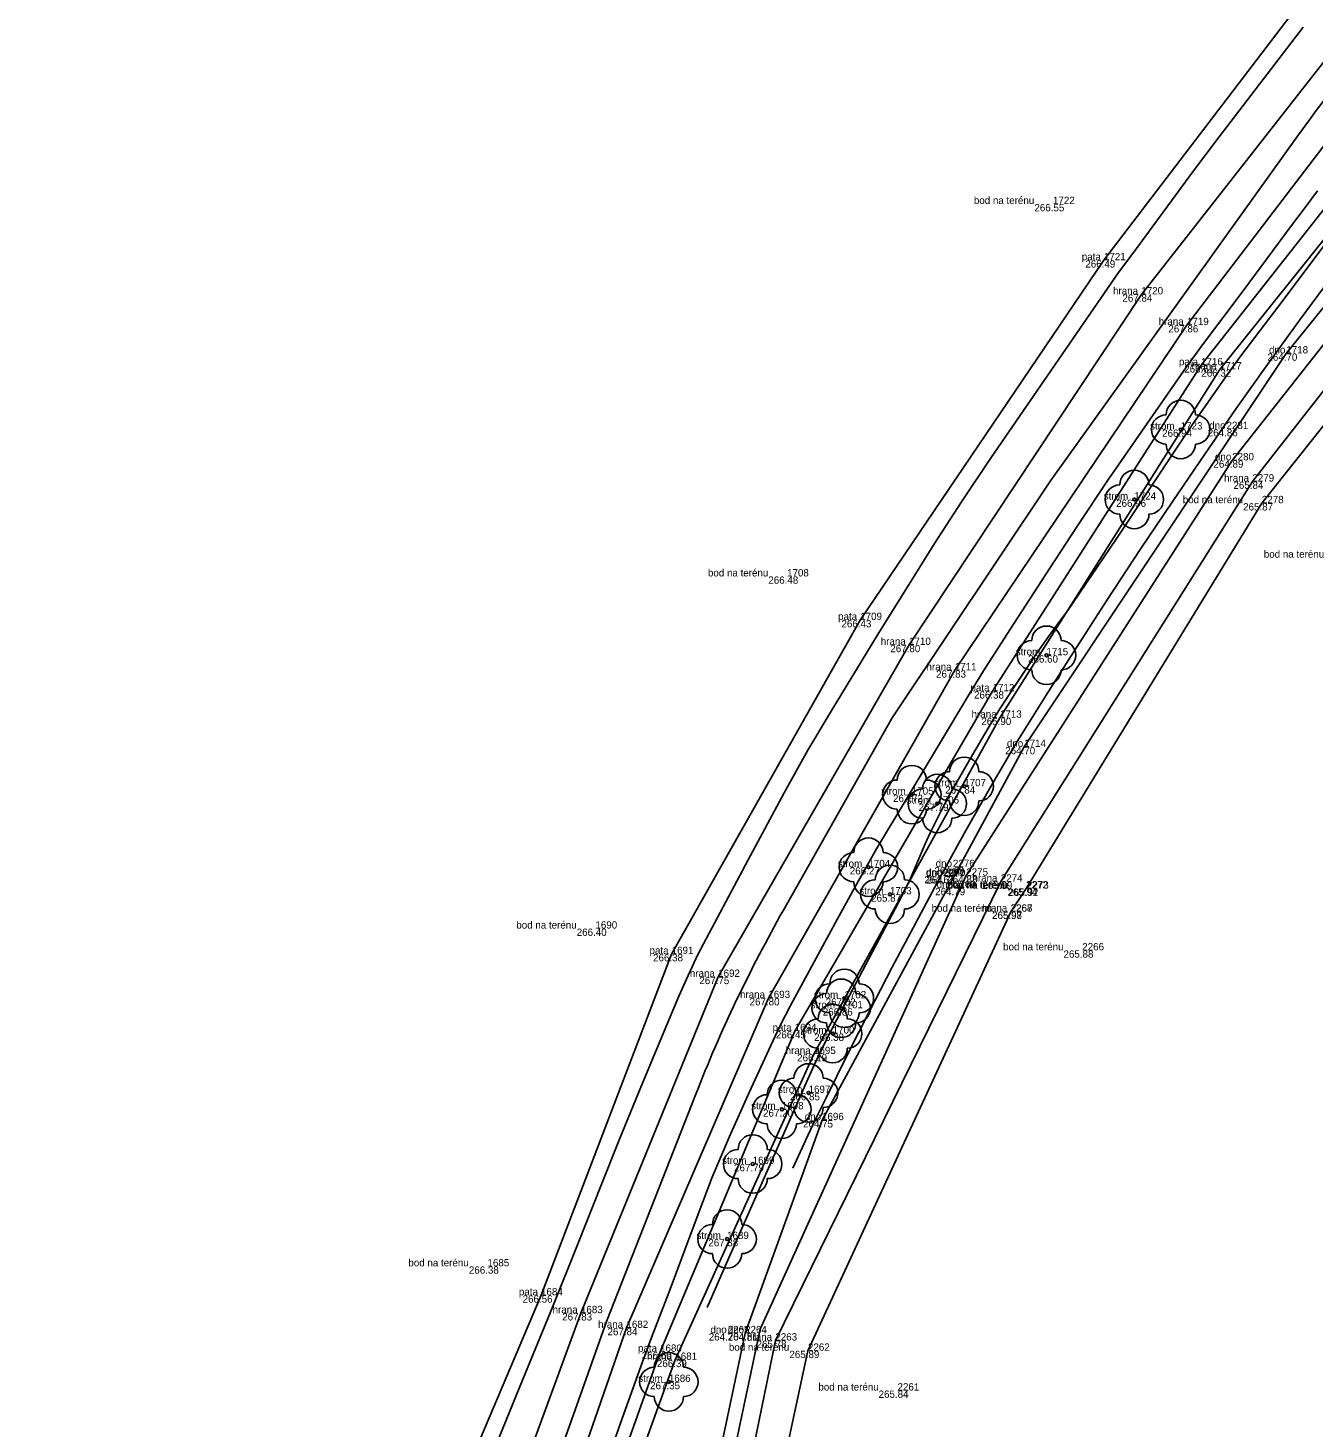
# Model space of a CAD drawing. Extents: x -567962 to -566460, y -1093720 to -1089838.
# Drawn here: x -567008.8 to -566920.9, y -1090322.4 to -1090226.7 of the extents above; entities that cross this region are included whole.
import ezdxf

# ---------------------------------------------------------------- set-up
doc = ezdxf.new("R2010")
doc.units = 0
for name, color, linetype in [('0_osa hráze', 7, 'Continuous'), ('bod_znacka', 7, 'Continuous'), ('cislo_bodu', 7, 'Continuous'), ('Doměření - kraj pole', 7, 'Continuous'), ('hlavni_vrst', 7, 'Continuous'), ('hrana_L', 7, 'Continuous'), ('hrana_P', 7, 'Continuous'), ('kod_bodu', 7, 'Continuous'), ('norm_vrst', 7, 'Continuous'), ('stromy', 7, 'Continuous'), ('vyska_bodu', 7, 'Continuous')]:
    doc.layers.add(name, color=color, linetype=linetype)

msp = doc.modelspace()

# ---------------------------------------------------------------- linework, layer by layer
at = {"layer": '0_osa hráze'}
for points in [[(-566921.908, -1090233.941), (-566938.917, -1090257.673), (-566949.741, -1090273.867), (-566957.169, -1090287.016)], [(-566963.167, -1090299.613), (-566969.274, -1090315.144), (-566984.132, -1090357.048), (-566990.346, -1090376.417)]]:
    msp.add_lwpolyline(points, dxfattribs=at)
for centre, radius, start, end in [((-566843.631, -1090289.76), 96.141, 137.41218, 144.50722), ((-566870.102, -1090336.202), 100, 150.5371, 158.53747)]:
    msp.add_arc(centre, radius, start, end, dxfattribs=at)
at = {"layer": 'bod_znacka'}
for p, q in [((-566938.74, -1090238.73), (-566938.74, -1090238.73)), ((-566935.26, -1090242.58), (-566935.26, -1090242.58)), ((-566932.7, -1090244.91), (-566932.7, -1090244.91)), ((-566929.58, -1090247.01), (-566929.58, -1090247.01)), ((-566928.62, -1090249.76), (-566928.62, -1090249.76)), ((-566922.79, -1090248.95), (-566922.79, -1090248.95)), ((-566927.33, -1090250.04), (-566927.33, -1090250.04)), ((-566930.01, -1090254.15), (-566930.01, -1090254.15)), ((-566926.88, -1090254.12), (-566926.88, -1090254.12)), ((-566926.49, -1090256.26), (-566926.49, -1090256.26)), ((-566925.11, -1090257.71), (-566925.11, -1090257.71)), ((-566933.18, -1090258.94), (-566933.18, -1090258.94)), ((-566924.46, -1090259.19), (-566924.46, -1090259.19)), ((-566956.92, -1090264.2), (-566956.92, -1090264.2)), ((-566951.92, -1090267.18), (-566951.92, -1090267.18)), ((-566948.58, -1090268.88), (-566948.58, -1090268.88)), ((-566939.19, -1090269.59), (-566939.19, -1090269.59)), ((-566945.45, -1090270.62), (-566945.45, -1090270.62)), ((-566942.87, -1090272.05), (-566942.87, -1090272.05)), ((-566942.37, -1090273.86), (-566942.37, -1090273.86)), ((-566940.71, -1090275.86), (-566940.71, -1090275.86)), ((-566948.39, -1090279.12), (-566948.39, -1090279.12)), ((-566944.81, -1090278.55), (-566944.81, -1090278.55)), ((-566946.65, -1090279.73), (-566946.65, -1090279.73)), ((-566951.36, -1090284.08), (-566951.36, -1090284.08)), ((-566945.58, -1090284.07), (-566945.58, -1090284.07)), ((-566946.25, -1090284.68), (-566946.25, -1090284.68)), ((-566946.22, -1090284.7), (-566946.22, -1090284.7)), ((-566944.67, -1090284.66), (-566944.67, -1090284.66)), ((-566942.31, -1090285.07), (-566942.31, -1090285.07)), ((-566949.89, -1090285.94), (-566949.89, -1090285.94)), ((-566945.51, -1090285.5), (-566945.51, -1090285.5)), ((-566940.57, -1090285.53), (-566940.57, -1090285.53)), ((-566940.52, -1090285.55), (-566940.52, -1090285.55)), ((-566941.64, -1090287.12), (-566941.64, -1090287.12)), ((-566941.63, -1090287.13), (-566941.63, -1090287.13)), ((-566970.02, -1090288.28), (-566970.02, -1090288.28)), ((-566936.74, -1090289.77), (-566936.74, -1090289.77)), ((-566964.81, -1090290.02), (-566964.81, -1090290.02)), ((-566961.63, -1090291.58), (-566961.63, -1090291.58)), ((-566958.2, -1090293.03), (-566958.2, -1090293.03)), ((-566953.22, -1090293.73), (-566953.22, -1090293.73)), ((-566953, -1090293.05), (-566953, -1090293.05)), ((-566956.4, -1090295.29), (-566956.4, -1090295.29)), ((-566953.8, -1090295.46), (-566953.8, -1090295.46)), ((-566955.08, -1090296.86), (-566955.08, -1090296.86)), ((-566955.45, -1090299.52), (-566955.45, -1090299.52)), ((-566957.28, -1090300.64), (-566957.28, -1090300.64)), ((-566954.53, -1090301.38), (-566954.53, -1090301.38)), ((-566959.27, -1090304.38), (-566959.27, -1090304.38)), ((-566961.02, -1090309.51), (-566961.02, -1090309.51)), ((-566977.4, -1090311.38), (-566977.4, -1090311.38)), ((-566973.74, -1090313.36), (-566973.74, -1090313.36)), ((-566971.01, -1090314.58), (-566971.01, -1090314.58)), ((-566967.9, -1090315.59), (-566967.9, -1090315.59)), ((-566960.98, -1090315.95), (-566960.98, -1090315.95)), ((-566959.79, -1090315.95), (-566959.79, -1090315.95)), ((-566957.72, -1090316.45), (-566957.72, -1090316.45)), ((-566965.6, -1090317.22), (-566965.6, -1090317.22)), ((-566955.49, -1090317.15), (-566955.49, -1090317.15)), ((-566964.56, -1090317.77), (-566964.56, -1090317.77)), ((-566965, -1090319.28), (-566965, -1090319.28)), ((-566949.37, -1090319.87), (-566949.37, -1090319.87))]:
    msp.add_line(p, q, dxfattribs=at)
at = {"layer": 'Doměření - kraj pole'}
msp.add_lwpolyline([(-567047.906, -1090663.012), (-567047.627, -1090662.294), (-567014.86, -1090563.09), (-567002.362, -1090535.532), (-566955.49, -1090317.15), (-566941.63, -1090287.13), (-566940.57, -1090285.53), (-566924.46, -1090259.19), (-566900.35, -1090228.87), (-566877.72, -1090206.37), (-566851.19, -1090186.75), (-566766.44, -1090128.68), (-566717.21, -1090096.34), (-566711.98, -1090092.48)], dxfattribs=at)
at = {"layer": 'hlavni_vrst'}
msp.add_lwpolyline([(-566956.533, -1090304.653), (-566955.502, -1090302.437), (-566954.903, -1090301.184), (-566954.247, -1090299.843), (-566952.78, -1090296.901), (-566951.278, -1090293.935), (-566949.727, -1090290.928), (-566948.124, -1090287.878), (-566946.45, -1090284.76), (-566945.538, -1090283.095), (-566944.699, -1090281.582), (-566942.982, -1090278.562), (-566941.254, -1090275.609), (-566939.214, -1090272.309), (-566937.349, -1090269.367), (-566935.033, -1090265.79), (-566932.772, -1090262.358), (-566930.554, -1090259.048), (-566928.368, -1090255.839), (-566926.209, -1090252.725), (-566924.067, -1090249.701), (-566921.855, -1090246.641), (-566919.79, -1090243.854)], dxfattribs=at)
at = {"layer": 'hrana_L'}
for p, q in [((-566920.16, -1090222.76), (-566935.26, -1090242.58)), ((-566932.7, -1090244.91), (-566917.27, -1090225.23)), ((-566914.61, -1090227.38), (-566929.58, -1090247.01)), ((-566912.62, -1090229.4), (-566928.62, -1090249.76)), ((-566927.33, -1090250.04), (-566911.56, -1090230.31)), ((-566935.26, -1090242.58), (-566951.92, -1090267.18)), ((-566948.58, -1090268.88), (-566932.7, -1090244.91)), ((-566945.45, -1090270.62), (-566929.58, -1090247.01)), ((-566928.62, -1090249.76), (-566942.87, -1090272.05)), ((-566942.37, -1090273.86), (-566927.33, -1090250.04)), ((-566964.81, -1090290.02), (-566951.92, -1090267.18)), ((-566948.58, -1090268.88), (-566961.63, -1090291.58)), ((-566945.45, -1090270.62), (-566958.2, -1090293.03)), ((-566942.87, -1090272.05), (-566956.4, -1090295.29)), ((-566955.08, -1090296.86), (-566942.37, -1090273.86)), ((-566973.74, -1090313.36), (-566964.81, -1090290.02)), ((-566971.01, -1090314.58), (-566961.63, -1090291.58)), ((-566967.9, -1090315.59), (-566958.2, -1090293.03)), ((-566956.4, -1090295.29), (-566965.6, -1090317.22)), ((-566964.56, -1090317.77), (-566955.08, -1090296.86)), ((-566973.74, -1090313.36), (-566985.01, -1090340.01)), ((-566971.01, -1090314.58), (-566980.92, -1090341.55)), ((-566977.18, -1090342.32), (-566967.9, -1090315.59)), ((-566965.6, -1090317.22), (-566974.91, -1090343.39)), ((-566974.3, -1090344.62), (-566964.56, -1090317.77))]:
    msp.add_line(p, q, dxfattribs=at)
for points in [[(-567053.87, -1090661.84), (-567020.06, -1090563.34), (-567005.258, -1090534.966), (-566958.763, -1090315.674), (-566944.67, -1090284.66), (-566926.49, -1090256.26), (-566902.65, -1090226.03), (-566881.28, -1090203.14), (-566853.44, -1090182.668), (-566715.257, -1090089.634)], [(-567050.54, -1090661.95), (-567017.83, -1090562.99), (-567002.61, -1090535.52), (-566957.72, -1090316.45), (-566942.31, -1090285.07), (-566925.11, -1090257.71), (-566901.37, -1090227.4), (-566879.5, -1090205.23), (-566852.16, -1090184), (-566767.57, -1090126.99), (-566713.28, -1090090.76)], [(-567054.63, -1090661.3), (-567021.1, -1090563.26), (-567005.966, -1090534.719), (-566959.79, -1090315.95), (-566954.53, -1090301.38)]]:
    msp.add_lwpolyline(points, dxfattribs=at)
at = {"layer": 'hrana_P'}
for p, q in [((-566922.79, -1090248.95), (-566910.59, -1090233.83)), ((-566940.71, -1090275.86), (-566922.79, -1090248.95)), ((-566954.53, -1090301.38), (-566940.71, -1090275.86))]:
    msp.add_line(p, q, dxfattribs=at)
at = {"layer": 'norm_vrst'}
for points in [[(-566921.631, -1090226.636), (-566927.374, -1090234.13), (-566929.214, -1090236.565), (-566930.144, -1090237.821), (-566933.286, -1090242.113), (-566934.252, -1090243.42), (-566942.963, -1090256.062), (-566945.005, -1090259.092), (-566946.842, -1090261.952), (-566950.762, -1090268.239), (-566953.91, -1090273.403), (-566955.496, -1090276.071), (-566957.12, -1090278.988), (-566959.578, -1090283.574), (-566963.014, -1090290.057), (-566963.692, -1090291.478), (-566964.311, -1090292.906), (-566965.735, -1090296.276), (-566967.081, -1090299.517), (-566968.372, -1090302.673), (-566969.588, -1090305.72), (-566971.236, -1090309.907), (-566972.962, -1090314.167), (-566974.958, -1090319.037), (-566976.818, -1090323.639)], [(-566969.913, -1090326.583), (-566968.088, -1090321.464), (-566966.795, -1090317.901), (-566966.181, -1090316.247), (-566964.978, -1090313.119), (-566963.904, -1090310.25), (-566963.004, -1090307.815), (-566962.031, -1090305.286), (-566960.849, -1090302.498), (-566959.504, -1090299.484), (-566958.039, -1090296.283), (-566957.4, -1090294.915), (-566956.691, -1090293.534), (-566953.476, -1090287.621), (-566952.352, -1090285.575), (-566950.796, -1090282.831), (-566948.721, -1090279.329), (-566944.417, -1090272.172), (-566943.482, -1090270.658), (-566941.698, -1090267.861), (-566938.962, -1090263.63), (-566937.068, -1090260.735), (-566935.032, -1090257.687), (-566932.881, -1090254.561), (-566929.611, -1090249.872), (-566928.521, -1090248.361), (-566925.741, -1090244.665), (-566922.499, -1090240.286), (-566921.513, -1090238.972), (-566920.65, -1090237.841)], [(-566962.371, -1090314.194), (-566961.149, -1090311.363), (-566955.495, -1090298.587), (-566954.946, -1090297.363), (-566954.195, -1090295.83), (-566953.545, -1090294.534), (-566949.312, -1090286.501), (-566948.564, -1090285.069), (-566947.67, -1090282.913), (-566947.482, -1090282.482), (-566947.131, -1090281.722), (-566946.382, -1090280.231), (-566945.807, -1090279.129), (-566944.249, -1090276.398), (-566942.942, -1090274.189), (-566942.37, -1090273.243), (-566941.418, -1090271.796), (-566939.949, -1090269.611), (-566938.981, -1090268.225), (-566938.226, -1090267.192), (-566937.801, -1090266.624), (-566934.432, -1090261.656), (-566930.188, -1090255.265), (-566929.157, -1090253.738), (-566926.997, -1090250.63), (-566925.963, -1090249.21), (-566922.93, -1090245.222), (-566917.696, -1090238.209)]]:
    msp.add_lwpolyline(points, dxfattribs=at)
at = {"layer": 'stromy'}
for centre in [(-566930.01, -1090254.15), (-566933.18, -1090258.94), (-566939.19, -1090269.59), (-566944.81, -1090278.55), (-566948.39, -1090279.12), (-566946.65, -1090279.73), (-566951.36, -1090284.08), (-566949.89, -1090285.94), (-566953.22, -1090293.73), (-566953, -1090293.05), (-566953.8, -1090295.46), (-566955.45, -1090299.52), (-566957.28, -1090300.64), (-566959.27, -1090304.38), (-566961.02, -1090309.51), (-566965, -1090319.28)]:
    msp.add_circle(centre, 0.1, dxfattribs=at)
for centre, start, end in [((-566930.01, -1090253.15), 0, 180), ((-566931.01, -1090254.15), 90, 270), ((-566929.01, -1090254.15), 270, 90), ((-566930.01, -1090255.15), 180, 0), ((-566933.18, -1090257.94), 0, 180), ((-566934.18, -1090258.94), 90, 270), ((-566932.18, -1090258.94), 270, 90), ((-566933.18, -1090259.94), 180, 0), ((-566939.19, -1090268.59), 0, 180), ((-566940.19, -1090269.59), 90, 270), ((-566938.19, -1090269.59), 270, 90), ((-566939.19, -1090270.59), 180, 0), ((-566944.81, -1090277.55), 0, 180), ((-566948.39, -1090278.12), 0, 180), ((-566949.39, -1090279.12), 90, 270), ((-566946.65, -1090278.73), 0, 180), ((-566947.39, -1090279.12), 270, 90), ((-566945.81, -1090278.55), 90, 270), ((-566943.81, -1090278.55), 270, 90), ((-566947.65, -1090279.73), 90, 270), ((-566945.65, -1090279.73), 270, 90), ((-566948.39, -1090280.12), 180, 0), ((-566944.81, -1090279.55), 180, 0), ((-566946.65, -1090280.73), 180, 0), ((-566951.36, -1090283.08), 0, 180), ((-566952.36, -1090284.08), 90, 270), ((-566950.36, -1090284.08), 270, 90), ((-566949.89, -1090284.94), 0, 180), ((-566951.36, -1090285.08), 180, 0), ((-566950.89, -1090285.94), 90, 270), ((-566948.89, -1090285.94), 270, 90), ((-566949.89, -1090286.94), 180, 0), ((-566953.22, -1090292.73), 0, 180), ((-566953, -1090292.05), 0, 180), ((-566954.22, -1090293.73), 90, 270), ((-566954, -1090293.05), 90, 270), ((-566952.22, -1090293.73), 270, 90), ((-566952, -1090293.05), 270, 90), ((-566953.8, -1090294.46), 0, 180), ((-566954.8, -1090295.46), 90, 270), ((-566953.22, -1090294.73), 180, 0), ((-566953, -1090294.05), 180, 0), ((-566952.8, -1090295.46), 270, 90), ((-566953.8, -1090296.46), 180, 0), ((-566955.45, -1090298.52), 0, 180), ((-566956.45, -1090299.52), 90, 270), ((-566954.45, -1090299.52), 270, 90), ((-566957.28, -1090299.64), 0, 180), ((-566958.28, -1090300.64), 90, 270), ((-566956.28, -1090300.64), 270, 90), ((-566955.45, -1090300.52), 180, 0), ((-566959.27, -1090303.38), 0, 180), ((-566957.28, -1090301.64), 180, 0), ((-566960.27, -1090304.38), 90, 270), ((-566958.27, -1090304.38), 270, 90), ((-566959.27, -1090305.38), 180, 0), ((-566961.02, -1090308.51), 0, 180), ((-566962.02, -1090309.51), 90, 270), ((-566960.02, -1090309.51), 270, 90), ((-566961.02, -1090310.51), 180, 0), ((-566965, -1090318.28), 0, 180), ((-566966, -1090319.28), 90, 270), ((-566964, -1090319.28), 270, 90), ((-566965, -1090320.28), 180, 0)]:
    msp.add_arc(centre, 1, start, end, dxfattribs=at)

# ---------------------------------------------------------------- texts
at = {"layer": 'cislo_bodu'}
for s, p in [('1722', (-566938.74, -1090238.73)), ('1721', (-566935.26, -1090242.58)), ('1720', (-566932.7, -1090244.91)), ('1719', (-566929.58, -1090247.01)), ('1718', (-566922.79, -1090248.95)), ('1716', (-566928.62, -1090249.76)), ('1717', (-566927.33, -1090250.04)), ('1723', (-566930.01, -1090254.15)), ('2281', (-566926.88, -1090254.12)), ('2280', (-566926.49, -1090256.26)), ('2279', (-566925.11, -1090257.71)), ('1724', (-566933.18, -1090258.94)), ('2278', (-566924.46, -1090259.19)), ('1708', (-566956.92, -1090264.2)), ('1709', (-566951.92, -1090267.18)), ('1710', (-566948.58, -1090268.88)), ('1715', (-566939.19, -1090269.59)), ('1711', (-566945.45, -1090270.62)), ('1712', (-566942.87, -1090272.05)), ('1713', (-566942.37, -1090273.86)), ('1714', (-566940.71, -1090275.86)), ('1707', (-566944.81, -1090278.55)), ('1705', (-566948.39, -1090279.12)), ('1706', (-566946.65, -1090279.73)), ('1704', (-566951.36, -1090284.08)), ('2271', (-566946.25, -1090284.68)), ('2270', (-566946.22, -1090284.7)), ('2276', (-566945.58, -1090284.07)), ('2275', (-566944.67, -1090284.66)), ('2269', (-566945.51, -1090285.5)), ('2274', (-566942.31, -1090285.07)), ('2272', (-566940.57, -1090285.53)), ('2273', (-566940.52, -1090285.55)), ('1703', (-566949.89, -1090285.94)), ('2268', (-566941.64, -1090287.12)), ('2267', (-566941.63, -1090287.13)), ('1690', (-566970.02, -1090288.28)), ('1691', (-566964.81, -1090290.02)), ('2266', (-566936.74, -1090289.77)), ('1692', (-566961.63, -1090291.58)), ('1693', (-566958.2, -1090293.03)), ('1702', (-566953, -1090293.05)), ('1701', (-566953.22, -1090293.73)), ('1694', (-566956.4, -1090295.29)), ('1700', (-566953.8, -1090295.46)), ('1695', (-566955.08, -1090296.86)), ('1697', (-566955.45, -1090299.52)), ('1698', (-566957.28, -1090300.64)), ('1696', (-566954.53, -1090301.38)), ('1699', (-566959.27, -1090304.38)), ('1689', (-566961.02, -1090309.51)), ('1685', (-566977.4, -1090311.38)), ('1684', (-566973.74, -1090313.36)), ('1683', (-566971.01, -1090314.58)), ('1682', (-566967.9, -1090315.59)), ('2265', (-566960.98, -1090315.95)), ('2264', (-566959.79, -1090315.95)), ('1680', (-566965.6, -1090317.22)), ('2263', (-566957.72, -1090316.45)), ('2262', (-566955.49, -1090317.15)), ('1681', (-566964.56, -1090317.77)), ('1686', (-566965, -1090319.28)), ('2261', (-566949.37, -1090319.87))]:
    msp.add_text(s, height=0.5, dxfattribs=at).set_placement(p)
at = {"layer": 'kod_bodu'}
for s, p in [('bod na terénu', (-566944.149, -1090238.73)), ('pata', (-566936.772, -1090242.58)), ('hrana', (-566934.637, -1090244.91)), ('hrana', (-566931.517, -1090247.01)), ('dno', (-566923.971, -1090248.95)), ('pata', (-566930.132, -1090249.76)), ('hrana', (-566929.267, -1090250.04)), ('dno', (-566928.061, -1090254.12)), ('strom', (-566932.104, -1090254.15)), ('dno', (-566927.671, -1090256.26)), ('hrana', (-566927.047, -1090257.71)), ('strom', (-566935.274, -1090258.94)), ('bod na terénu', (-566929.869, -1090259.19)), ('bod na terénu', (-566924.329, -1090262.92)), ('bod na terénu', (-566962.329, -1090264.2)), ('pata', (-566953.432, -1090267.18)), ('hrana', (-566950.517, -1090268.88)), ('strom', (-566941.284, -1090269.59)), ('hrana', (-566947.387, -1090270.62)), ('pata', (-566944.382, -1090272.05)), ('hrana', (-566944.307, -1090273.86)), ('dno', (-566941.891, -1090275.86)), ('strom', (-566946.904, -1090278.55)), ('strom', (-566950.484, -1090279.12)), ('strom', (-566948.744, -1090279.73)), ('strom', (-566953.454, -1090284.08)), ('dno', (-566947.431, -1090284.68)), ('dno', (-566947.401, -1090284.7)), ('dno', (-566946.761, -1090284.07)), ('dno', (-566945.851, -1090284.66)), ('dno', (-566946.691, -1090285.5)), ('bod na terénu', (-566945.979, -1090285.53)), ('bod na terénu', (-566945.929, -1090285.55)), ('hrana', (-566944.247, -1090285.07)), ('strom', (-566951.984, -1090285.94)), ('bod na terénu', (-566947.039, -1090287.13)), ('hrana', (-566943.577, -1090287.12)), ('bod na terénu', (-566975.429, -1090288.28)), ('pata', (-566966.322, -1090290.02)), ('bod na terénu', (-566942.149, -1090289.77)), ('hrana', (-566963.567, -1090291.58)), ('hrana', (-566960.137, -1090293.03)), ('strom', (-566955.094, -1090293.05)), ('strom', (-566955.314, -1090293.73)), ('pata', (-566957.912, -1090295.29)), ('strom', (-566955.894, -1090295.46)), ('hrana', (-566957.017, -1090296.86)), ('strom', (-566957.544, -1090299.52)), ('strom', (-566959.374, -1090300.64)), ('dno', (-566955.711, -1090301.38)), ('strom', (-566961.364, -1090304.38)), ('strom', (-566963.114, -1090309.51)), ('bod na terénu', (-566982.809, -1090311.38)), ('pata', (-566975.252, -1090313.36)), ('hrana', (-566972.947, -1090314.58)), ('hrana', (-566969.837, -1090315.59)), ('dno', (-566962.161, -1090315.95)), ('dno', (-566960.971, -1090315.95)), ('pata', (-566967.112, -1090317.22)), ('bod na terénu', (-566960.899, -1090317.15)), ('hrana', (-566959.657, -1090316.45)), ('hrana', (-566966.497, -1090317.77)), ('strom', (-566967.094, -1090319.28)), ('bod na terénu', (-566954.779, -1090319.87))]:
    msp.add_text(s, height=0.5, dxfattribs=at).set_placement(p)
at = {"layer": 'vyska_bodu'}
for s, p in [('266.55', (-566940.01, -1090239.23)), ('266.49', (-566936.53, -1090243.08)), ('267.84', (-566933.995, -1090245.41)), ('267.86', (-566930.852, -1090247.51)), ('266.61', (-566929.769, -1090250.26)), ('264.70', (-566924.083, -1090249.45)), ('266.32', (-566928.6, -1090250.54)), ('266.94', (-566931.28, -1090254.65)), ('264.86', (-566928.161, -1090254.62)), ('264.89', (-566927.771, -1090256.76)), ('265.84', (-566926.403, -1090258.21)), ('266.96', (-566934.426, -1090259.44)), ('265.87', (-566925.743, -1090259.69)), ('266.48', (-566958.201, -1090264.7)), ('266.43', (-566953.201, -1090267.68)), ('267.80', (-566949.861, -1090269.38)), ('266.60', (-566940.446, -1090270.09)), ('267.83', (-566946.733, -1090271.12)), ('266.38', (-566944.14, -1090272.55)), ('265.90', (-566943.638, -1090274.36)), ('264.70', (-566942.003, -1090276.36)), ('267.72', (-566949.675, -1090279.62)), ('267.84', (-566946.105, -1090279.05)), ('267.79', (-566947.923, -1090280.23)), ('266.27', (-566952.632, -1090284.58)), ('264.69', (-566946.85, -1090284.57)), ('264.67', (-566947.533, -1090285.18)), ('264.71', (-566947.407, -1090285.2)), ('264.83', (-566945.963, -1090285.16)), ('265.99', (-566943.568, -1090285.57)), ('265.87', (-566951.173, -1090286.44)), ('264.79', (-566946.793, -1090286)), ('265.94', (-566941.851, -1090286.03)), ('265.92', (-566941.79, -1090286.05)), ('265.98', (-566942.91, -1090287.62)), ('265.97', (-566942.902, -1090287.63)), ('266.40', (-566971.299, -1090288.78)), ('265.88', (-566938.021, -1090290.27)), ('266.38', (-566966.08, -1090290.52)), ('267.75', (-566962.915, -1090292.08)), ('267.80', (-566959.481, -1090293.53)), ('266.86', (-566954.478, -1090294.23)), ('267.02', (-566954.281, -1090293.55)), ('266.45', (-566957.681, -1090295.79)), ('266.38', (-566955.07, -1090295.96)), ('266.19', (-566956.23, -1090297.36)), ('266.85', (-566956.72, -1090300.02)), ('267.20', (-566958.561, -1090301.14)), ('264.75', (-566955.825, -1090301.88)), ('267.79', (-566960.543, -1090304.88)), ('267.38', (-566962.303, -1090310.01)), ('266.38', (-566978.67, -1090311.88)), ('266.56', (-566974.998, -1090313.86)), ('267.83', (-566972.293, -1090315.08)), ('267.84', (-566969.195, -1090316.09)), ('264.70', (-566962.273, -1090316.45)), ('264.81', (-566960.975, -1090316.45)), ('265.78', (-566959.003, -1090316.95)), ('266.60', (-566966.856, -1090317.72)), ('265.89', (-566956.76, -1090317.65)), ('266.39', (-566965.818, -1090318.27)), ('267.35', (-566966.283, -1090319.78)), ('265.84', (-566950.663, -1090320.37))]:
    msp.add_text(s, height=0.5, dxfattribs=at).set_placement(p)

doc.saveas('drawing.dxf')
